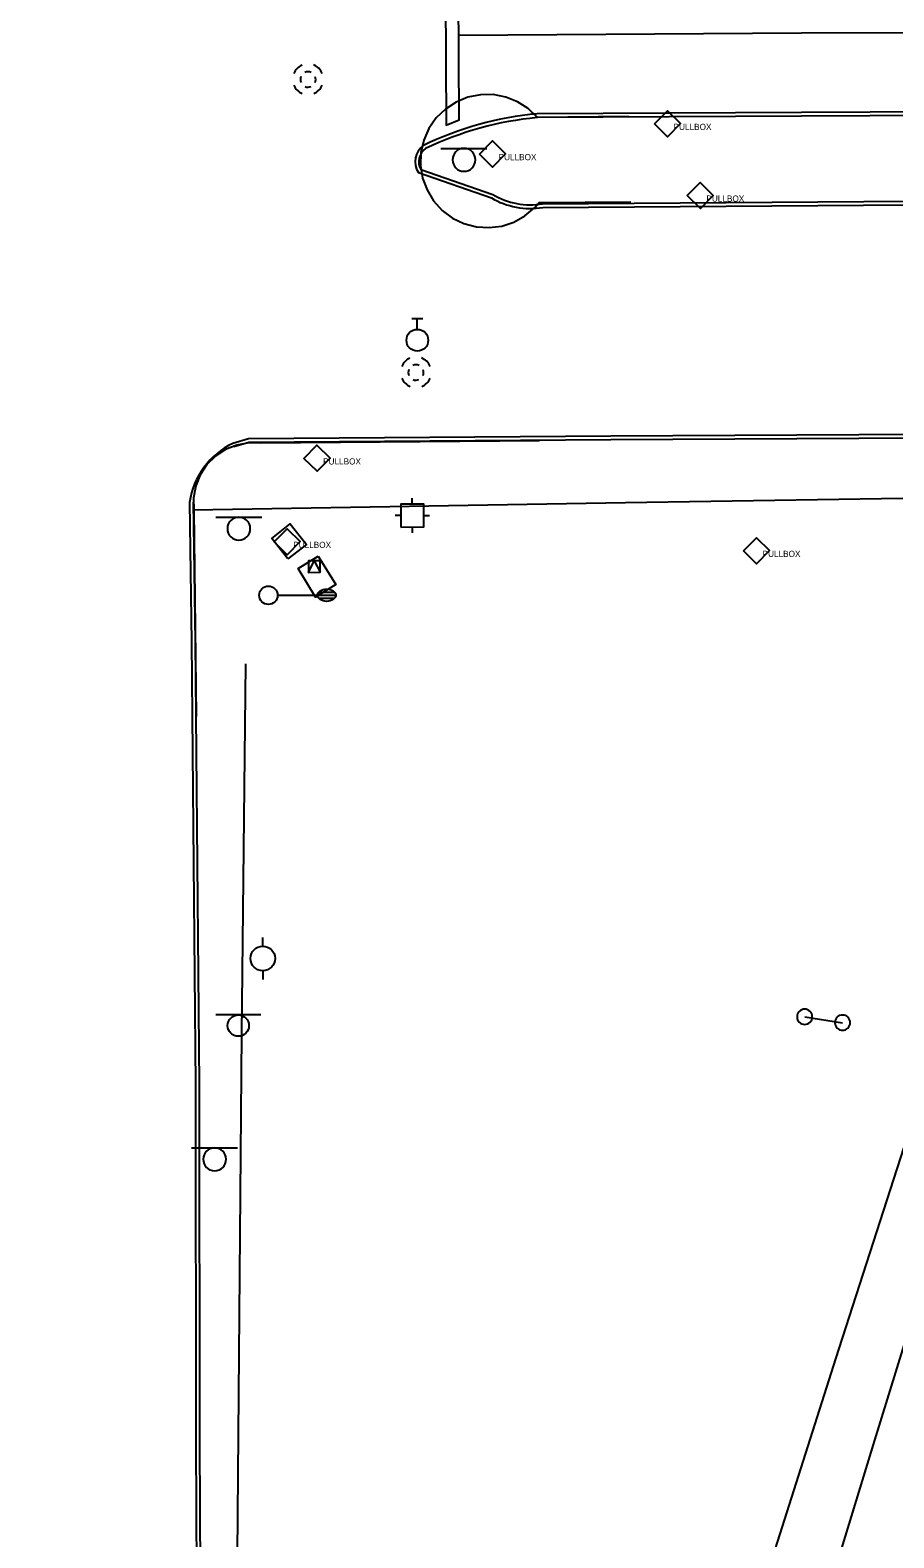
# Model space of a CAD drawing. Extents: x 2145380 to 2156929, y 139568 to 149130.
# Drawn here: x 2150877.7 to 2151018.5, y 148060.5 to 148306.1 of the extents above; entities that cross this region are included whole.
import ezdxf

# ---------------------------------------------------------------- set-up
doc = ezdxf.new("R2010")
doc.units = 0
for name, color, linetype in [('Default', 7, 'Continuous'), ('TOPO_Asphalt', 7, 'Continuous'), ('TOPO_Concrete', 7, 'Continuous'), ('TOPO_Curb Back', 7, 'Continuous'), ('TOPO_DRAIN_Manhole', 7, 'Continuous'), ('TOPO_Fence', 7, 'Continuous'), ('TOPO_Light Pole', 7, 'Continuous'), ('TOPO_Misc', 7, 'Continuous'), ('TOPO_Misc Line', 7, 'Continuous'), ('TOPO_Power Pole', 7, 'Continuous'), ('TOPO_Power Pullbox', 7, 'Continuous'), ('TOPO_Sidewalk', 7, 'Continuous'), ('TOPO_Sign', 7, 'Continuous'), ('TOPO_Traffic Signal', 7, 'Continuous'), ('TOPO_Water Valve', 7, 'Continuous')]:
    doc.layers.add(name, color=color, linetype=linetype)

# ---------------------------------------------------------------- blocks, each defined once
blk = doc.blocks.new('MHEXST')
at = {"layer": 'TOPO_DRAIN_Manhole'}
for centre, radius, start, end in [((-0.1, 0.3), 12.7, 112.9748, 158.2636), ((-0.1, 0.1), 6.35, 157.9722, 204.161), ((-0.1, 0.1), 6.35, 66.1941, 113.691), ((-0.1, 0.3), 12.7, 22.0744, 68.6991), ((-0.1, 0.1), 6.35, 336.8023, 21.4046), ((-0.1, 0.3), 12.7, 202.6921, 248.1938), ((-0.1, 0.1), 6.35, 248.5791, 293.1995), ((-0.1, 0.3), 12.7, 291.7963, 337.3032)]:
    blk.add_arc(centre, radius, start, end, dxfattribs=at)
blk = doc.blocks.new('TRFSIG')
at = {"layer": 'TOPO_Traffic Signal'}
for p, q in [((0.04, 4.66), (0.04, 7.04)), ((-4.7, -0.09), (-7.08, -0.09)), ((0.04, -4.83), (0.04, -7.22)), ((4.79, -0.09), (7.17, -0.09))]:
    blk.add_line(p, q, dxfattribs=at)
blk.add_lwpolyline([(-4.7, -4.85), (4.81, -4.83), (4.79, 4.67), (-4.72, 4.66), (-4.7, -4.85)], dxfattribs=at)
blk = doc.blocks.new('POST')
at = {"layer": 'TOPO_Misc'}
for start, end in [(89.99996, 180.00004), (179.99996, 270.00004), (359.99996, 90.00004), (269.99996, 0.00004)]:
    blk.add_arc((-0.01, 0.03), 3.16, start, end, dxfattribs=at)
blk = doc.blocks.new('POWPOL')
at = {"layer": 'TOPO_Power Pole'}
for p, q in [((0, 10.2), (0, 17.3)), ((0, -10.2), (0, -17.3))]:
    blk.add_line(p, q, dxfattribs=at)
blk.add_circle((0, 0), 10.2, dxfattribs=at)
blk = doc.blocks.new('LP')
at = {"layer": 'TOPO_Light Pole'}
blk.add_line((3.81, 0), (20.32, 0), dxfattribs=at)
for points in [[(20.32, 0), (27.94, 0)], [(20.32, 0), (23.5, 0)], [(20.83, 1.27), (27.43, 1.27)], [(20.83, 1.27), (23.5, 1.27)], [(23.71, 1.27), (27.43, 1.27)], [(23.71, 0), (27.94, 0)], [(20.83, -1.27), (27.43, -1.27)], [(20.83, -1.27), (23.5, -1.27)], [(23.71, -1.27), (27.43, -1.27)]]:
    blk.add_lwpolyline(points, dxfattribs=at)
blk.add_circle((0, 0), 3.81, dxfattribs=at)
blk.add_ellipse((24.13, 0), major_axis=(3.81, 0), ratio=0.666667, dxfattribs=at)
blk = doc.blocks.new('pulbox')
at = {"layer": 'Default'}
blk.add_lwpolyline([(-5.38, -0.01), (-0.02, 5.42), (5.4, 0.06), (0.05, -5.36), (-5.38, -0.01)], dxfattribs=at)
blk.add_text('PULLBOX', height=2.54, dxfattribs=at).set_placement((2.54, -2.54))
blk = doc.blocks.new('EXSIGN')
at = {"layer": 'Default'}
blk.add_line((9.3, 4.42), (-9.3, 4.42), dxfattribs=at)
blk.add_circle((0, 0), 4.42, dxfattribs=at)
blk = doc.blocks.new('WATVAL')
at = {"layer": 'Default'}
for p, q in [((-2.25, 9), (2.25, 9)), ((0, 4.5), (0, 9))]:
    blk.add_line(p, q, dxfattribs=at)
blk.add_circle((0, 0), 4.5, dxfattribs=at)

msp = doc.modelspace()

# ---------------------------------------------------------------- linework, layer by layer
at = {"layer": 'TOPO_Asphalt'}
for points in [[(2151048.85, 148184), (2151038.82, 148151.82), (2151027.63, 148116.14), (2151015.13, 148075.66), (2151005.17, 148043.12), (2150995.4, 148010.66), (2150984.05, 147971.82), (2150972.73, 147932.1), (2150964.84, 147904.22), (2150955.62, 147870.36), (2150950.07, 147849.17), (2150943.21, 147823.16), (2150936.37, 147796.39), (2150929.01, 147767.19), (2150918.46, 147723.8), (2150908.78, 147682.5), (2150900.73, 147647.64), (2150892.14, 147609.87), (2150886.78, 147584.79)], [(2151031.67, 148167), (2151033.43, 148166.33), (2151027.46, 148146.36), (2151020.11, 148124.12), (2151008.99, 148089.63), (2150994.98, 148045.56), (2150984.37, 148009.67), (2150975.99, 147980.79), (2150967.87, 147952.18), (2150961.61, 147930.52), (2150953.44, 147900.67), (2150941.73, 147859), (2150931.26, 147819.05), (2150925.77, 147796.82), (2150920.97, 147778.05), (2150913.77, 147749.06), (2150908.39, 147727.91), (2150899.16, 147689.08), (2150893.03, 147662.48), (2150888.79, 147643.68), (2150883.83, 147620.67), (2150877.99, 147590.63)]]:
    msp.add_lwpolyline(points, dxfattribs=at)
msp.add_arc((2150916.22, 148227.33), 12.67, 115.7636, 171.7753, dxfattribs=at)
at = {"layer": 'TOPO_Concrete'}
for points in [[(2150919.71, 148219.93), (2150917.08, 148223.26), (2150920.09, 148225.63), (2150922.72, 148222.3), (2150919.71, 148219.93)], [(2150924.64, 148220.38), (2150927.52, 148215.75), (2150924.23, 148213.71), (2150921.36, 148218.34), (2150924.64, 148220.38)]]:
    msp.add_lwpolyline(points, dxfattribs=at)
at = {"layer": 'TOPO_Curb Back'}
for points in [[(2150975.26, 148291.98), (2150960.4, 148291.84), (2150958.9, 148293.28), (2150957.15, 148294.4), (2150955.22, 148295.17), (2150953.17, 148295.56), (2150951.09, 148295.55), (2150949.05, 148295.15), (2150947.12, 148294.36), (2150945.38, 148293.22), (2150943.89, 148291.77), (2150942.7, 148290.06), (2150941.86, 148288.15), (2150941.4, 148286.12), (2150941.34, 148284.04), (2150941.67, 148281.98), (2150942.39, 148280.03), (2150943.47, 148278.25), (2150944.87, 148276.71), (2150946.54, 148275.46), (2150948.41, 148274.56), (2150950.43, 148274.03), (2150952.51, 148273.89), (2150954.57, 148274.15), (2150956.55, 148274.81), (2150958.36, 148275.82), (2150959.95, 148277.17), (2150960.68, 148277.99), (2150975.6, 148278.09)], [(2151070.47, 148292.99), (2151003.44, 148292.66), (2150960.33, 148292.42)], [(2151070.29, 148292.39), (2151003.44, 148292.06), (2150960.36, 148291.82)], [(2150940.98, 148282.88), (2150952.88, 148278.76)], [(2150941.38, 148283.38), (2150953.14, 148279.31)], [(2150961.21, 148277.79), (2151065.99, 148278.51)], [(2150961.26, 148277.19), (2151065.8, 148277.91)], [(2150960.71, 148239.16), (2150915.3, 148238.76), (2150913.33, 148238.82), (2150911.39, 148238.48), (2150909.56, 148237.75), (2150907.91, 148236.68), (2150906.52, 148235.29), (2150905.43, 148233.64), (2150904.69, 148231.82), (2150904.34, 148229.88), (2150904.38, 148227.92), (2150904.73, 148194.28)], [(2151054.16, 148240.3), (2151032.98, 148240.23), (2150972.34, 148239.95), (2150913.27, 148239.49), (2150910.71, 148238.74)], [(2151053.97, 148239.7), (2151032.98, 148239.63), (2150972.34, 148239.35), (2150913.36, 148238.89), (2150910.87, 148238.17)], [(2150903.67, 148229.14), (2150903.99, 148206.41), (2150904.63, 148134.28), (2150904.69, 148075.98), (2150904.97, 148022.25), (2150905.72, 147948.26), (2150905.28, 147881.1), (2150903.34, 147822.79), (2150899.75, 147773.61), (2150894.39, 147718.98), (2150886.44, 147665.58), (2150875.76, 147606.6), (2150867.8, 147565.67)], [(2150904.27, 148229.15), (2150904.59, 148206.42), (2150905.23, 148134.28), (2150905.29, 148075.99), (2150905.57, 148022.26), (2150906.32, 147948.26), (2150905.88, 147881.09), (2150903.94, 147822.76), (2150900.35, 147773.56), (2150894.98, 147718.91), (2150887.03, 147665.49), (2150876.35, 147606.49), (2150868.41, 147565.66)]]:
    msp.add_lwpolyline(points, dxfattribs=at)
for centre, radius, start, end in [((2150965.23, 148238.89), 53.76, 95.2286, 115.8064), ((2150965.23, 148238.89), 53.15, 95.2554, 115.7524), ((2150943.67, 148284.64), 3.22, 124.9486, 213.1843), ((2150943.67, 148284.64), 2.62, 125.9505, 208.9026), ((2150959.21, 148289.43), 12.41, 239.3103, 279.4942), ((2150959.21, 148289.43), 11.81, 239.0196, 279.7226)]:
    msp.add_arc(centre, radius, start, end, dxfattribs=at)
at = {"layer": 'TOPO_Fence'}
msp.add_lwpolyline([(2150909.97, 147870.56), (2150910.14, 147913.99), (2150911.08, 147986.58), (2150911.52, 148057.68), (2150912.2, 148142.54), (2150912.87, 148202.84)], dxfattribs=at)
at = {"layer": 'TOPO_Misc'}
msp.add_lwpolyline([(2150923.08, 148217.74), (2150924.96, 148217.75), (2150924.95, 148219.62), (2150923.08, 148219.62), (2150923.08, 148217.74), (2150924.02, 148219.62), (2150924.96, 148217.75)], dxfattribs=at)
at = {"layer": 'TOPO_Misc Line'}
msp.add_lwpolyline([(2150945.29, 148332.86), (2150945.51, 148290.58), (2150947.63, 148291.45), (2150947.4, 148332.87)], close=True, dxfattribs=at)
msp.add_lwpolyline([(2151074.44, 148305.81), (2151003.42, 148305.59), (2150947.55, 148305.2)], dxfattribs=at)
at = {"layer": 'TOPO_Sidewalk'}
msp.add_lwpolyline([(2150904.29, 148227.93), (2150974.73, 148229.13), (2151033.89, 148230.06)], dxfattribs=at)
at = {"layer": 'TOPO_Sign'}
for points in [[(2150944.66, 148286.81), (2150952.16, 148286.81)], [(2150948.41, 148286.8), (2150948.41, 148286.8)], [(2150946.55, 148284.94), (2150946.55, 148284.94)], [(2150948.41, 148283.07), (2150948.41, 148283.07)], [(2150950.28, 148284.94), (2150950.28, 148284.94)], [(2150907.96, 148226.72), (2150915.45, 148226.73)], [(2150911.71, 148226.72), (2150911.71, 148226.72)], [(2150909.84, 148224.86), (2150909.84, 148224.86)], [(2150913.58, 148224.86), (2150913.58, 148224.86)], [(2150911.71, 148222.99), (2150911.71, 148222.99)], [(2151003.96, 148145.33), (2151010.13, 148144.37)], [(2150904.02, 148123.98), (2150911.52, 148123.99)], [(2150907.77, 148123.98), (2150907.77, 148123.98)], [(2150905.9, 148122.12), (2150905.9, 148122.12)], [(2150909.64, 148122.12), (2150909.64, 148122.12)], [(2150907.77, 148120.25), (2150907.77, 148120.25)]]:
    msp.add_lwpolyline(points, dxfattribs=at)
for centre, start, end in [((2150948.41, 148284.94), 90, 180), ((2150948.41, 148284.94), 360, 90), ((2150948.41, 148284.94), 180, 270), ((2150948.41, 148284.94), 270, 0), ((2150911.71, 148224.86), 90, 180), ((2150911.71, 148224.86), 360, 90), ((2150911.71, 148224.86), 180, 270), ((2150911.71, 148224.86), 270, 0), ((2150907.77, 148122.12), 90, 180), ((2150907.77, 148122.12), 360, 90), ((2150907.77, 148122.12), 180, 270), ((2150907.77, 148122.12), 270, 0)]:
    msp.add_arc(centre, 1.87, start, end, dxfattribs=at)

# ---------------------------------------------------------------- block references
at = {"layer": 'TOPO_DRAIN_Manhole', "xscale": 0.19685000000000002, "yscale": 0.19685000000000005}
for p in [(2150923.01, 148298.01), (2150940.61, 148250.28)]:
    msp.add_blockref('MHEXST', p, dxfattribs=at)
at = {"layer": 'TOPO_Light Pole', "xscale": 0.39370000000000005, "yscale": 0.3937000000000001}
msp.add_blockref('LP', (2150916.53, 148214.01), dxfattribs=at)
at = {"layer": 'TOPO_Misc', "xscale": 0.39370000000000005, "yscale": 0.3937000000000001}
for name, p in [('EXSIGN', (2150911.62, 148143.9)), ('POST', (2151003.96, 148145.33)), ('POST', (2151010.13, 148144.37))]:
    msp.add_blockref(name, p, dxfattribs=at)
at = {"layer": 'TOPO_Power Pole', "xscale": 0.19685000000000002, "yscale": 0.19685000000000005}
msp.add_blockref('POWPOL', (2150915.61, 148154.84), dxfattribs=at)
at = {"layer": 'TOPO_Power Pullbox', "xscale": 0.39370000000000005, "yscale": 0.3937000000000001}
for p in [(2150981.59, 148290.81), (2150953.06, 148285.88), (2150986.94, 148279.13), (2150924.45, 148236.31), (2150919.58, 148222.72), (2150996.1, 148221.25)]:
    msp.add_blockref('pulbox', p, dxfattribs=at)
at = {"layer": 'TOPO_Traffic Signal', "xscale": 0.39370000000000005, "yscale": 0.3937000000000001}
msp.add_blockref('TRFSIG', (2150939.98, 148227.03), dxfattribs=at)
at = {"layer": 'TOPO_Water Valve', "xscale": 0.39370000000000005, "yscale": 0.3937000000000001}
msp.add_blockref('WATVAL', (2150940.81, 148255.54), dxfattribs=at)

doc.saveas('drawing.dxf')
